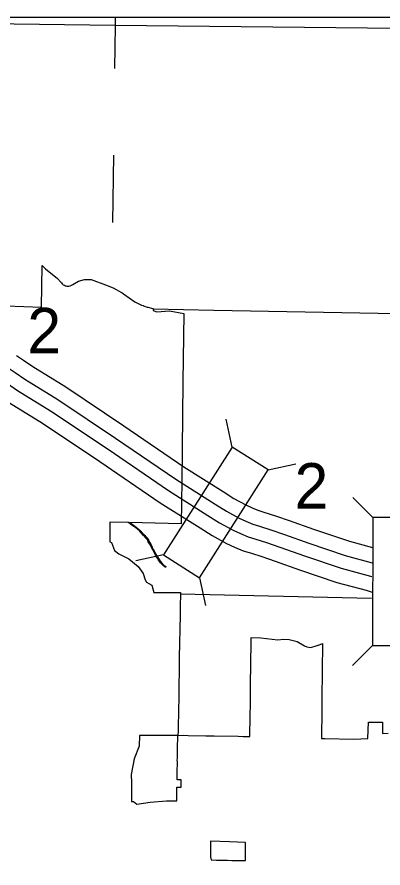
# Model space of a CAD drawing. Extents: x 309389.3 to 309420.2, y 336441.4 to 336461.2.
# Drawn here: x 309390.828 to 309391.343, y 336458.653 to 336459.85 of the extents above; entities that cross this region are included whole.
import ezdxf

# ---------------------------------------------------------------- set-up
doc = ezdxf.new("R2010")
doc.units = 0
for name, color, linetype in [('Level 37', 7, 'Continuous'), ('Level 4', 7, 'Continuous'), ('Level 62', 7, 'Continuous'), ('R_Erosion', 7, 'Continuous'), ('R_MOT', 7, 'Continuous')]:
    doc.layers.add(name, color=color, linetype=linetype)

msp = doc.modelspace()

# ---------------------------------------------------------------- linework, layer by layer
at = {"layer": 'Level 37'}
for p, q in [((309391.1314, 336459.245), (309391.1228, 336459.2841)), ((309391.1314, 336459.245), (309391.1228, 336459.2841)), ((309391.1819, 336459.2127), (309391.221, 336459.2213)), ((309391.1819, 336459.2127), (309391.221, 336459.2213)), ((309391.3292, 336459.1458), (309391.301, 336459.1742)), ((309391.3292, 336459.1458), (309391.301, 336459.1742)), ((309391.0344, 336459.0933), (309390.9954, 336459.0847)), ((309391.0344, 336459.0933), (309390.9954, 336459.0847)), ((309391.085, 336459.061), (309391.0936, 336459.022)), ((309391.085, 336459.061), (309391.0936, 336459.022)), ((309391.3287, 336458.9658), (309391.3003, 336458.9376)), ((309391.3287, 336458.9658), (309391.3003, 336458.9376))]:
    msp.add_line(p, q, dxfattribs=at)
for points in [[(309391.085, 336459.061), (309391.1819, 336459.2127), (309391.1314, 336459.245), (309391.0344, 336459.0933)], [(309391.085, 336459.061), (309391.1819, 336459.2127), (309391.1314, 336459.245), (309391.0344, 336459.0933)], [(309391.3887, 336458.9657), (309391.3892, 336459.1457), (309391.3292, 336459.1458), (309391.3287, 336458.9658)], [(309391.3887, 336458.9657), (309391.3892, 336459.1457), (309391.3292, 336459.1458), (309391.3287, 336458.9658)]]:
    msp.add_lwpolyline(points, close=True, dxfattribs=at)
at = {"layer": 'Level 4'}
for points in [[(309390.9664, 336459.8498), (309390.9663, 336459.8373), (309390.9655, 336459.7776)], [(309390.9664, 336459.8498), (309390.9663, 336459.8373), (309390.9655, 336459.7776)], [(309390.4604, 336459.846), (309390.6118, 336459.843), (309390.9661, 336459.8382), (309391.3663, 336459.8343), (309391.7738, 336459.8244), (309392.0498, 336459.8199)], [(309390.964, 336459.6554), (309390.9628, 336459.5608)], [(309391.1056, 336459.4371), (309391.02, 336459.4388)], [(309391.9449, 336459.4225), (309391.7684, 336459.4275), (309391.3626, 336459.4321), (309391.1056, 336459.4371)], [(309391.0583, 336459.0385), (309391.3271, 336459.0326)], [(309391.0583, 336459.0385), (309391.3271, 336459.0326)]]:
    msp.add_lwpolyline(points, dxfattribs=at)
at = {"layer": 'Level 62'}
for points in [[(309390.7628, 336459.4454), (309390.8628, 336459.4415), (309390.8638, 336459.5005), (309390.8683, 336459.4957), (309390.8855, 336459.4818), (309390.8898, 336459.4772), (309390.8908, 336459.4757), (309390.8921, 336459.4743), (309390.8935, 336459.4732), (309390.895, 336459.4724), (309390.8965, 336459.4718), (309390.8971, 336459.4717), (309390.8972, 336459.4716), (309390.8984, 336459.4714), (309390.8999, 336459.4713), (309390.9012, 336459.4714), (309390.9031, 336459.4719), (309390.9043, 336459.4723), (309390.9053, 336459.4728), (309390.9068, 336459.4738), (309390.915, 336459.4783), (309390.9234, 336459.4806), (309390.9329, 336459.4806), (309390.9529, 336459.4732), (309390.9635, 336459.4687), (309390.9755, 336459.4623), (309390.976, 336459.4622), (309390.9783, 336459.4605), (309390.9943, 336459.4491), (309391, 336459.4463), (309391.0015, 336459.4456), (309391.0036, 336459.4445), (309391.0057, 336459.4438), (309391.0065, 336459.4436), (309391.0116, 336459.4419), (309391.0124, 336459.4416), (309391.0197, 336459.4399), (309391.0201, 336459.4399), (309391.02, 336459.4373), (309391.0199, 336459.4369), (309391.0253, 336459.435), (309391.043, 336459.4366), (309391.0631, 336459.4326), (309391.0619, 336459.3368), (309391.0608, 336459.2418), (309391.0602, 336459.193), (309391.06, 336459.1717), (309391.0599, 336459.1673), (309391.06, 336459.1665), (309391.0596, 336459.1371), (309391.0047, 336459.1384), (309390.9872, 336459.1388), (309390.9922, 336459.1352), (309390.9961, 336459.1323), (309391.0018, 336459.1276), (309391.0074, 336459.1215), (309391.0108, 336459.1177), (309391.0133, 336459.1145), (309391.014, 336459.1124), (309391.0172, 336459.1075), (309391.0185, 336459.1043), (309391.0187, 336459.1038), (309391.0202, 336459.1008), (309391.0213, 336459.0989), (309391.0235, 336459.095), (309391.0251, 336459.0921), (309391.0262, 336459.0903), (309391.0265, 336459.0898), (309391.0283, 336459.0868), (309391.0299, 336459.0846), (309391.0327, 336459.081), (309391.0335, 336459.0804), (309391.0348, 336459.0789), (309391.0379, 336459.0767)], [(309391.0379, 336459.0767), (309391.0372, 336459.0757), (309391.034, 336459.0782), (309391.0318, 336459.0805), (309391.0304, 336459.0822), (309391.0275, 336459.0859), (309391.0259, 336459.0885), (309391.0239, 336459.0918), (309391.0231, 336459.0932), (309391.0213, 336459.0965), (309391.0193, 336459.1002), (309391.0175, 336459.1036), (309391.0162, 336459.107), (309391.0131, 336459.1117), (309391.0123, 336459.1139), (309391.0102, 336459.1165), (309391.0066, 336459.1206), (309391.0008, 336459.127), (309390.9981, 336459.1292), (309390.9951, 336459.1316), (309390.9916, 336459.1342), (309390.9883, 336459.1365), (309390.9853, 336459.1388), (309390.9845, 336459.1388), (309390.9592, 336459.1394), (309390.9589, 336459.1137), (309390.9589, 336459.1116), (309390.9612, 336459.1105), (309390.9658, 336459.0996), (309390.9715, 336459.0947), (309390.9857, 336459.0879), (309390.9991, 336459.077), (309391.0061, 336459.0672), (309391.0087, 336459.058), (309391.0104, 336459.0551), (309391.0138, 336459.0529), (309391.0181, 336459.0508), (309391.021, 336459.0405), (309391.024, 336459.0405), (309391.0387, 336459.0404), (309391.0583, 336459.0402), (309391.0579, 336459.0186), (309391.0578, 336459.0091), (309391.0567, 336458.949), (309391.0566, 336458.9377), (309391.0561, 336458.9021), (309391.0559, 336458.8887), (309391.0558, 336458.8787), (309391.0553, 336458.8459), (309391.0546, 336458.8394), (309391.0625, 336458.8395), (309391.0693, 336458.8394), (309391.094, 336458.8389), (309391.0977, 336458.8389), (309391.1059, 336458.8388), (309391.1397, 336458.8381), (309391.1467, 336458.8379), (309391.1521, 336458.8379), (309391.156, 336458.8377), (309391.1561, 336458.844), (309391.1564, 336458.8614), (309391.1568, 336458.8893), (309391.1568, 336458.8922), (309391.1569, 336458.899), (309391.1569, 336458.8997), (309391.157, 336458.9064), (309391.1572, 336458.9143), (309391.1575, 336458.9361), (309391.158, 336458.9744), (309391.158, 336458.9769), (309391.1717, 336458.9766), (309391.1955, 336458.9736), (309391.2033, 336458.9747), (309391.2115, 336458.9742), (309391.2227, 336458.9712), (309391.2332, 336458.9655), (309391.2361, 336458.9639), (309391.2416, 336458.9629), (309391.248, 336458.9648), (309391.2522, 336458.9663), (309391.2526, 336458.9664), (309391.2585, 336458.9684), (309391.2585, 336458.9645), (309391.258, 336458.9343), (309391.2573, 336458.8864), (309391.2573, 336458.8849), (309391.2573, 336458.8824), (309391.2572, 336458.8711), (309391.2568, 336458.839), (309391.2568, 336458.8349), (309391.2615, 336458.8348), (309391.3024, 336458.8342), (309391.3221, 336458.8348), (309391.3229, 336458.8579), (309391.3394, 336458.8579), (309391.3427, 336458.858), (309391.3429, 336458.848), (309391.3429, 336458.842), (309391.3509, 336458.8424)]]:
    msp.add_lwpolyline(points, dxfattribs=at)
for points in [[(309391.0546, 336458.8394), (309391.0061, 336458.839), (309391.001, 336458.839), (309391.0001, 336458.824), (309390.9931, 336458.8065), (309390.9892, 336458.7844), (309390.9895, 336458.7727), (309390.9897, 336458.7464), (309390.9924, 336458.7463), (309390.9968, 336458.7425), (309391.0158, 336458.7456), (309391.0386, 336458.7475), (309391.0532, 336458.7471), (309391.0532, 336458.7507), (309391.0534, 336458.7606), (309391.0535, 336458.7653), (309391.0535, 336458.7667), (309391.0592, 336458.7666), (309391.0594, 336458.7768), (309391.0537, 336458.7769), (309391.0537, 336458.7775), (309391.0538, 336458.7824), (309391.0539, 336458.7872), (309391.054, 336458.7921), (309391.0541, 336458.7969), (309391.0542, 336458.8018), (309391.054, 336458.8049), (309391.0541, 336458.8067), (309391.0541, 336458.8115), (309391.0542, 336458.8164), (309391.0543, 336458.8212), (309391.0544, 336458.8261), (309391.0545, 336458.8335)], [(309391.149, 336458.6633), (309391.1498, 336458.6636), (309391.15, 336458.6844), (309391.1501, 336458.6888), (309391.1273, 336458.6895), (309391.1008, 336458.6904), (309391.1008, 336458.688), (309391.1007, 336458.6815), (309391.1008, 336458.6751), (309391.1009, 336458.6687), (309391.1018, 336458.6641), (309391.1093, 336458.664), (309391.1187, 336458.6638), (309391.1246, 336458.6637), (309391.1305, 336458.6636), (309391.1366, 336458.6635), (309391.1426, 336458.6635)]]:
    msp.add_lwpolyline(points, close=True, dxfattribs=at)
at = {"layer": 'R_Erosion'}
for points in [[(309390.6899, 336459.4103), (309390.7157, 336459.403), (309390.7504, 336459.3933), (309390.7698, 336459.3849), (309390.782, 336459.378), (309390.7918, 336459.3721), (309390.8019, 336459.3663), (309390.8158, 336459.3564), (309390.8256, 336459.3498), (309390.8392, 336459.3405), (309390.8858, 336459.3119), (309390.9672, 336459.2576), (309391.0518, 336459.1998), (309391.1073, 336459.1648), (309391.1231, 336459.1547), (309391.1411, 336459.1448), (309391.1506, 336459.1405), (309391.1602, 336459.1363), (309391.1697, 336459.1336), (309391.1857, 336459.1285), (309391.2047, 336459.1219), (309391.239, 336459.1097), (309391.2901, 336459.0926), (309391.3283, 336459.0823)], [(309390.8276, 336459.3735), (309390.8373, 336459.367), (309390.8506, 336459.358), (309390.897, 336459.3294), (309390.9788, 336459.2749), (309391.0632, 336459.2172), (309391.1184, 336459.1824), (309391.1337, 336459.1727), (309391.1505, 336459.1635), (309391.1591, 336459.1595), (309391.1672, 336459.156), (309391.1758, 336459.1535), (309391.1922, 336459.1483), (309391.2116, 336459.1416), (309391.2458, 336459.1293), (309391.2961, 336459.1125), (309391.3287, 336459.1037)], [(309390.815, 336459.3341), (309390.8289, 336459.3246), (309390.8756, 336459.2959), (309390.9566, 336459.2419), (309391.0414, 336459.184), (309391.0971, 336459.1488), (309391.1134, 336459.1384), (309391.1326, 336459.1279), (309391.1429, 336459.1232), (309391.1538, 336459.1185), (309391.1643, 336459.1154), (309391.1797, 336459.1106), (309391.1984, 336459.104), (309391.2328, 336459.0918), (309391.2846, 336459.0744), (309391.3258, 336459.0633), (309391.3277, 336459.0627)], [(309390.8176, 336459.3071), (309390.8643, 336459.2784), (309390.9449, 336459.2246), (309391.0299, 336459.1666), (309391.086, 336459.1313), (309391.1028, 336459.1205), (309391.1232, 336459.1093), (309391.1344, 336459.1041), (309391.1467, 336459.0988), (309391.1582, 336459.0955), (309391.1731, 336459.0908), (309391.1915, 336459.0844), (309391.226, 336459.0721), (309391.2786, 336459.0545), (309391.3198, 336459.0434), (309391.3281, 336459.0406)]]:
    msp.add_lwpolyline(points, dxfattribs=at)
at = {"layer": 'R_MOT'}
msp.add_lwpolyline([(309389.3351, 336459.8498), (309394.8545, 336459.8498), (309394.8545, 336455.3696), (309389.3351, 336455.3696)], close=True, dxfattribs=at)

# ---------------------------------------------------------------- texts
at = {"layer": 'Level 37'}
for p in [(309390.8429, 336459.3766), (309391.2189, 336459.1583)]:
    msp.add_text('2', height=0.064, dxfattribs=at).set_placement(p)

doc.saveas('drawing.dxf')
